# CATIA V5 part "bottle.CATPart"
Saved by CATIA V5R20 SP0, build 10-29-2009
Part number: 饮料瓶
Material "Summer sky"
Bounding box of the stored display mesh (mm): x -25 to 26, y -25 to 25, z 0 to 110
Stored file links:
  F:\bottle.CATPart
  D:\CATIA\win_b64\startup\materials\Catalog.CATMaterial
  D:\CATIA\win_b64\startup\materials\yellow_env_512x512.jpg
  D:\CATIA\win_b64\startup\materials\red_env_512x512.jpg
  D:\CATIA\win_b64\startup\materials\alpin_fir.jpg
  D:\CATIA\win_b64\startup\materials\summer_sky.jpg
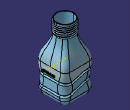
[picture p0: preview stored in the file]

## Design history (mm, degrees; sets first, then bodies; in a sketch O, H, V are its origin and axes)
Set1
  Sketch1 on xy-plane, origin (0, 0, 0), H (1, 0, 0), V (0, 1, 0)
    point P1 (0, 0)
    line L1 (25, 25) -> (25, -25)
    line L2 (25, -25) -> (-25, -25)
    line L3 (-25, -25) -> (-25, 25)
    line L4 (-25, 25) -> (25, 25)
    length L1 = 50
    length L4 = 50
    coincidence: P1 V, P1 H
    vertical: L1 V, L3 V
    horizontal: L2 H, L4 H
    equidistance: L1 L3 P1, L2 L4 P1
  Sketch2 on face of Pad1 from Sketch1.L2, origin (0, -25, 0), H (1, 0, 0), V (0, 0, 1)
    spline S1 through (-48.822, 0) (-10.1473, 23.8211) (12.744, 16.6738) (57.9052, 27.3431)
    point P1 (-48.822, 0)
    coincidence: P1 H
  Extrude1: Element1 Sketch2, Lim1 60, Lim2 60
  MultiSel1: CommonCtxFeats ({extract ExtractElem face of Pad1 from Sketch1.L4}; {extract ExtractElem face of Fillet1}; {extract ExtractElem face of Pad1 from Sketch1.L3}; {extract ExtractElem face of Fillet1}; {extract ExtractElem face of Pad1 from Sketch1.L2}; {extract ExtractElem face of Fillet1}; {extract ExtractElem face of Pad1 from Sketch1.L1}; {extract ExtractElem face of Fillet1})
  Sketch3 on face of Pad1 from Sketch1.L2, origin (0, -25, 0), H (1, 0, 0), V (0, 0, 1)
    spline S1 through (-34.0063, 29.5181) (-13.3283, 38.6631) (8.749, 33.2381) (34.5577, 36.0281)
  Extrude2: Element1 Sketch3, Lim1 60, Lim2 60
  MultiSel2: CommonCtxFeats ({extract ExtractElem face of Pad1 from Sketch1.L2}; {extract ExtractElem face of Fillet1}; {extract ExtractElem face of Pad1 from Sketch1.L1}; {extract ExtractElem face of Fillet1}; {extract ExtractElem face of Pad1 from Sketch1.L4}; {extract ExtractElem face of Fillet1}; {extract ExtractElem face of Pad1 from Sketch1.L3}; {extract ExtractElem face of Fillet1})
  Join1: Elements ({intersect ToIntersect1 {extract ExtractElem face of Pad1 from Sketch1.L2}, ToIntersect2 Extrude2}; {intersect ToIntersect1 {extract ExtractElem face of Fillet1}, ToIntersect2 Extrude2}; {intersect ToIntersect1 {extract ExtractElem face of Pad1 from Sketch1.L1}, ToIntersect2 Extrude2}; {intersect ToIntersect1 {extract ExtractElem face of Fillet1}, ToIntersect2 Extrude2}; {intersect ToIntersect1 {extract ExtractElem face of Pad1 from Sketch1.L4}, ToIntersect2 Extrude2}; {intersect ToIntersect1 {extract ExtractElem face of Fillet1}, ToIntersect2 Extrude2}; {intersect ToIntersect1 {extract ExtractElem face of Pad1 from Sketch1.L3}, ToIntersect2 Extrude2}; {intersect ToIntersect1 {extract ExtractElem face of Fillet1}, ToIntersect2 Extrude2})
  Join2: Elements {intersect ToIntersect1 Fillet1, ToIntersect2 Extrude1}
  Join3: Elements ({intersect ToIntersect1 {extract ExtractElem face of Pad1 from Sketch1.L4}, ToIntersect2 Extrude1}; {intersect ToIntersect1 {extract ExtractElem face of Fillet1}, ToIntersect2 Extrude1}; {intersect ToIntersect1 {extract ExtractElem face of Pad1 from Sketch1.L3}, ToIntersect2 Extrude1}; {intersect ToIntersect1 {extract ExtractElem face of Fillet1}, ToIntersect2 Extrude1}; {intersect ToIntersect1 {extract ExtractElem face of Pad1 from Sketch1.L2}, ToIntersect2 Extrude1}; {intersect ToIntersect1 {extract ExtractElem face of Fillet1}, ToIntersect2 Extrude1}; {intersect ToIntersect1 {extract ExtractElem face of Pad1 from Sketch1.L1}, ToIntersect2 Extrude1}; {intersect ToIntersect1 {extract ExtractElem face of Fillet1}, ToIntersect2 Extrude1})
  Plane1: type Normal, Curve Join3, RefPoint vertex [face of MultiSel1 | face of MultiSel1]
  Circle1: type CtrRad, Start 0, End 180, Center vertex [face of MultiSel1 | face of MultiSel1], Support Plane1, Radius 2, FirstDirection (0, 1, 0)
  Plane2: type Normal, Curve Join1, RefPoint vertex [face of MultiSel2 | face of MultiSel2]
  Circle2: type CtrRad, Start 0, End 180, Center vertex [face of MultiSel2 | face of MultiSel2], Support Plane2, Radius 2, FirstDirection (0, 1, 0)
Body1 (main body), material "Summer sky"
  Pad1: profile Sketch1, direction (0, 0, 1), length 50
  Fillet1: on edge [face of Pad1 from Sketch1.L4 | face of Pad1 from Sketch1.L1]; edge [face of Pad1 from Sketch1.L3 | face of Pad1 from Sketch1.L4]; edge [face of Pad1 from Sketch1.L1 | face of Pad1 from Sketch1.L2]; edge [face of Pad1 from Sketch1.L2 | face of Pad1 from Sketch1.L3]
  Fillet2: radius 8, on start face of Pad1
  Plane3: type Offset, RefPlane end face of Pad1, Offset 40, reversed
  Sketch4 on Plane3, origin (0, 0, 90), H (1, 0, 0), V (0, -1, 0)
    circle A1 centre (0, 0) radius 15
  Pad2: profile Sketch4, direction (0, 0, 1), length 20
  Sketch5 on start face of Pad2, origin (0, 0, 90), H (1, 0, 0), V (0, -1, 0)
    point P1 (15, 0)
    distance P1 V = 15
    coincidence: P1 H
  Sketch6 on end face of Pad1, origin (0, 0, 50), H (1, 0, 0), V (0, 1, 0)
    point P1 (25, 0)
    distance P1 V = 25
    coincidence: P1 H
  Sketch7 on end face of Pad1, origin (0, 0, 50), H (1, 0, 0), V (0, 1, 0)
  Loft1: solid, Sections ({boundary Boundary {extract ExtractElem end face of Pad1}}; {boundary Boundary {extract ExtractElem start face of Pad2}}), StartFace end face of Pad1, EndFace start face of Pad2
  Slot1: profile Circle2, centre curve Join1
  Slot2: profile Circle1, centre curve Join3
  Shell1: IntOffset 1, Face end face of Pad2, ExtOffset 0
  Helix1: Direction Z axis, RefPoint Sketch5, Pitch 3, Height 18, TaperAngle 0
  Point1: type OnCurve, Support Helix1, RefPoint vertex of Helix1, Length -5
  Line1: type PtDir, RefPoint vertex of Helix1, Direction (1, 0, 0), Start 0, End 10
  Connect1: Curve1 Line1, Point1 vertex of Line1, Tension1 1, Curve2 Helix1, Point2 Point1, Tension2 1
  Point2: type OnCurve, Support Connect1, RefPoint Sketch5, Length -5
  Line2: type PtDir, RefPoint Sketch5, Direction (1, 0, 0), Start 0, End 10
  Connect2: Curve1 Line2, Point1 vertex of Line2, Tension1 1, Curve2 Connect1, Point2 Point2, Tension2 1
  Plane4: type Normal, Curve Connect2, RefPoint vertex of Connect1
  Circle3: type CtrRad, Start 0, End 180, Center vertex of Connect1, Support Plane4, Radius 1, FirstDirection (0, -1, 0)
  Rib1: profile Circle3, centre curve Connect2
  Body2
    Sketch8 on Plane3, origin (0, 0, 90), H (1, 0, 0), V (0, -1, 0)
      circle A1 centre (0, 0) radius 14
      polyline C1
      polyline C2
      polyline C3
      polyline C4
      polyline C5
      polyline C6
      polyline C7
      polyline C8
      polyline C9
      polyline C10
      polyline C11
      radius A1 = 14
    Pad3: profile Sketch8, direction (0, 0, -1), length 20, mirrored extent
  Remove1: tool Body2
  Sketch9 on face of Pad1 from Sketch1.L1, origin (25, 0, 0), H (0, 1, 0), V (0, 0, 1)
    polyline C1
    polyline C2
    polyline C3
    polyline C4
    polyline C5
    polyline C6
    polyline C7
    polyline C8
    polyline C9
    polyline C10
    polyline C11
  Pad4: profile Sketch9, direction (1, 0, 0), length 1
